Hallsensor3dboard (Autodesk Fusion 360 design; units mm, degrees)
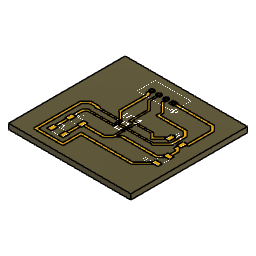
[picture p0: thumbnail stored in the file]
sketch "Outline" plane through (0, 0, 0) normal (0, 0, 1) x axis (1, 0, 0)
  line L1 (34.27, 6.35) -> (0, 6.35)
  line L2 (34.27, 39.04) -> (34.27, 6.35)
  line L3 (0, 39.04) -> (34.27, 39.04)
  line L4 (0, 6.35) -> (0, 39.04)
canvas "Canvas1" bodies "Board"
canvas "Canvas2" bodies "Board"
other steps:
extrude "Extrude1" sketch "Outline" blind 1.5 bodies "Board"
pcbextrude "PCBExtrude1"
pcbextrude "PCBExtrude1"
pcbextrude "PCBExtrude1"
pcbextrude "PCBExtrude2" bodies "CopperHoles"
create_component "CreateComponent1"
create_component "CreateComponent2"
create_component "CreateComponent3"
create_component "CreateComponent4"
as_built_joint "As-built1"
named bodies: "Board", "CopperHoles"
